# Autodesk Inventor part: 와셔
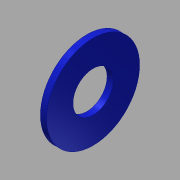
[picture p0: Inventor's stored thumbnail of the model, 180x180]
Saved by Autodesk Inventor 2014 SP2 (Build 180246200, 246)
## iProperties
Created: 2015-12
Part Number: 와셔
Material: 스테인리스강
Document SubType Name: Modeling
Designer: mduedu
Density: 8.08 g/cm^3
Appearance: 파란색 - 벽 페인트 - 광택
Author: mduedu
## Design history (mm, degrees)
sketch "스케치1"
  geometry: C1 r 3.25 at (0, 0); C2 r 7.5 at (0, 0); 1 further point
  constraints: 2 centre point, 2 coincident
  dimensions: "d0" = 6.5 diameter of C1; "d1" = 15 diameter of C2
extrude "돌출1" new body sketch "스케치1" stored distance "d2" = 1; taper "d3" = 0 deg
node "솔리드1"
